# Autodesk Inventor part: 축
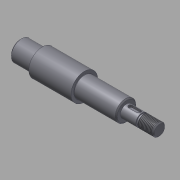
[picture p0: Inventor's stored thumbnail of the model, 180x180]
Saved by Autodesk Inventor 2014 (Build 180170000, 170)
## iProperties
Created: 2015-12
Part Number: 축
Material: 강철, 연강
Document SubType Name: Modeling
Designer: mdu
Density: 7.86 g/cm^3
Appearance: Steel
CustomPartVersion: 1
Author: mdu
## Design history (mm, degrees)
sketch "스케치5"
  geometry: L1 (0, 0)-(135, 0); L2 (0, 0)-(135, 0); L3 (135, 0)-(135, 6); L4 (103, 6)-(103, 10); L5 (103, 10)-(62, 10); L6 (62, 10)-(62, 13); L7 (62, 13)-(21, 13); L8 (21, 13)-(21, 10); L9 (21, 10)-(0, 10); L10 (0, 10)-(0, 0); L11 (118, 6)-(118, 5); L12 (118, 5)-(120, 5); L13 (120, 5)-(120, 6); L14 (135, 6)-(120, 6); L15 (118, 6)-(103, 6)
  constraints: 31 end point, 12 perpendicular, 9 parallel, 1 collinear, 1 horizontal
  dimensions: "d43" = 20 diameter of L9 L1; "d44" = 26 diameter of L7 L1; "d45" = 20 diameter of L5 L2; "d47" = 41 distance of L6.end L7.end; "d48" = 32 distance between parallel lines of L3 L4; "d50" = 21 distance of L8.end L9.end; "d52" = 12 diameter of L14 L1; "d53" = 15 distance between parallel lines of L3 L13; "d54" = 2 distance of L11.end L12.end; "d55" = 1 distance between parallel lines of L14 L12; "d64" = 135 distance of L1.start L1.end
revolve "회전4" sketch "스케치5" stored, may be unused: angle "d51" = 90 deg
feature "스레드6" dims "d56" = 10, "d57" = 0
chamfer "모따기6" distance "d32" = 1; stored, may be unused: second distance "d33" = 0.4, angle "d34" = 45 deg
chamfer "모따기5" distance "d27" = 1; stored, may be unused: second distance "d28" = 0.125, angle "d29" = 45 deg
fillet "모깎기1" dims "d17" = 0.3
fillet "모깎기2" dims "d18" = 0.3
chamfer "모따기3" distance "d19" = 1; stored, may be unused: second distance "d20" = 1, angle "d21" = 45 deg
node "작업 평면1"
sketch "스케치6"
  geometry: L1 (-3.5, 2)-(4.5, 2); L2 (4.5, -2)-(-3.5, -2); L3 (-7.5, 9)-(-7.5, -9) reference; A1 r 2 centre (4.5, 0) between (4.5, -2) and (4.5, 2); A2 r 2 centre (-3.5, 0) between (-3.5, 2) and (-3.5, -2); 1 further point
  constraints: 4 end point, 4 point on circle, 4 tangent, 2 centre point, 1 horizontal, 1 horizontal alignment, 1 parallel
  dimensions: "d59" = 2 distance edge to line of A2 L3; "d60" = 12 dimension on A1 A2; "d61" = 4 distance between parallel lines of L2 L1
extrude "돌출1" cut sketch "스케치6" distance "d62" = 2.3; taper "d63" = 0 deg
node "솔리드1"
node "솔리드2"
other parameters: "d46" = 12
